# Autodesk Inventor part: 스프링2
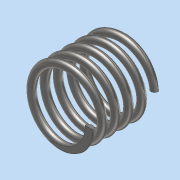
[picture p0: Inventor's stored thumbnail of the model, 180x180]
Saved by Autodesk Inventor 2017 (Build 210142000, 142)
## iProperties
Part Number: 스프링2
Material: 스테인레스 스틸
Document SubType Name: Modeling
Designer: MRC
Density: 8 g/cm^3
Appearance: 반연마
Mass: 6.55763 g
Surface Area: 16.7052 cm^2
Volume: 0.819704 cm^3
Author: MRC
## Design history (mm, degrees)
sketch "스케치1"
  geometry: L1 (0, 0)-(0, 17.5); L2 (0, 0)-(8.5, 0); L3 (0, 17.5)-(8.5, 17.5); C1 r 1 at (8.5, 0)
  constraints: 6 end point, 2 horizontal, 1 centre point, 1 coincident, 1 parallel, 1 vertical
  dimensions: "d0" = 17.5 distance of L1.start L1.end (derived); "d1" = 17 diameter of L2.end L1; "d2" = 2 diameter of C1
feature "코일1" sketch "스케치1" pitch "d3" = 10; turns "d5" = 5; dims "d4" = 17.5 (= d0), "d6" = 0, angle "d7" = 90 deg, angle "d8" = 90 deg, "d9" = 0, "d10" = 0
sketch "스케치2"
  geometry: L1 (17.5, 14.331)-(0, 14.331); L2 (0, 14.331)-(0, -14.331); L3 (0, -14.331)-(17.5, -14.331); L4 (17.5, -14.331)-(17.5, 14.331); 2 further points
  constraints: 8 end point, 2 parallel, 1 coincident, 1 horizontal, 1 midpoint, 1 perpendicular
  dimensions: "d11" = 28.66142 distance of L3.end L1.start; "d12" = 17.5 distance of L2.end L3.end (= d0)
extrude "돌출1" sketch "스케치2" stored distance "d13" = 0; taper "d14" = 0 deg
node "솔리드1"
